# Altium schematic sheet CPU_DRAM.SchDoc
size 381 x 635 mm
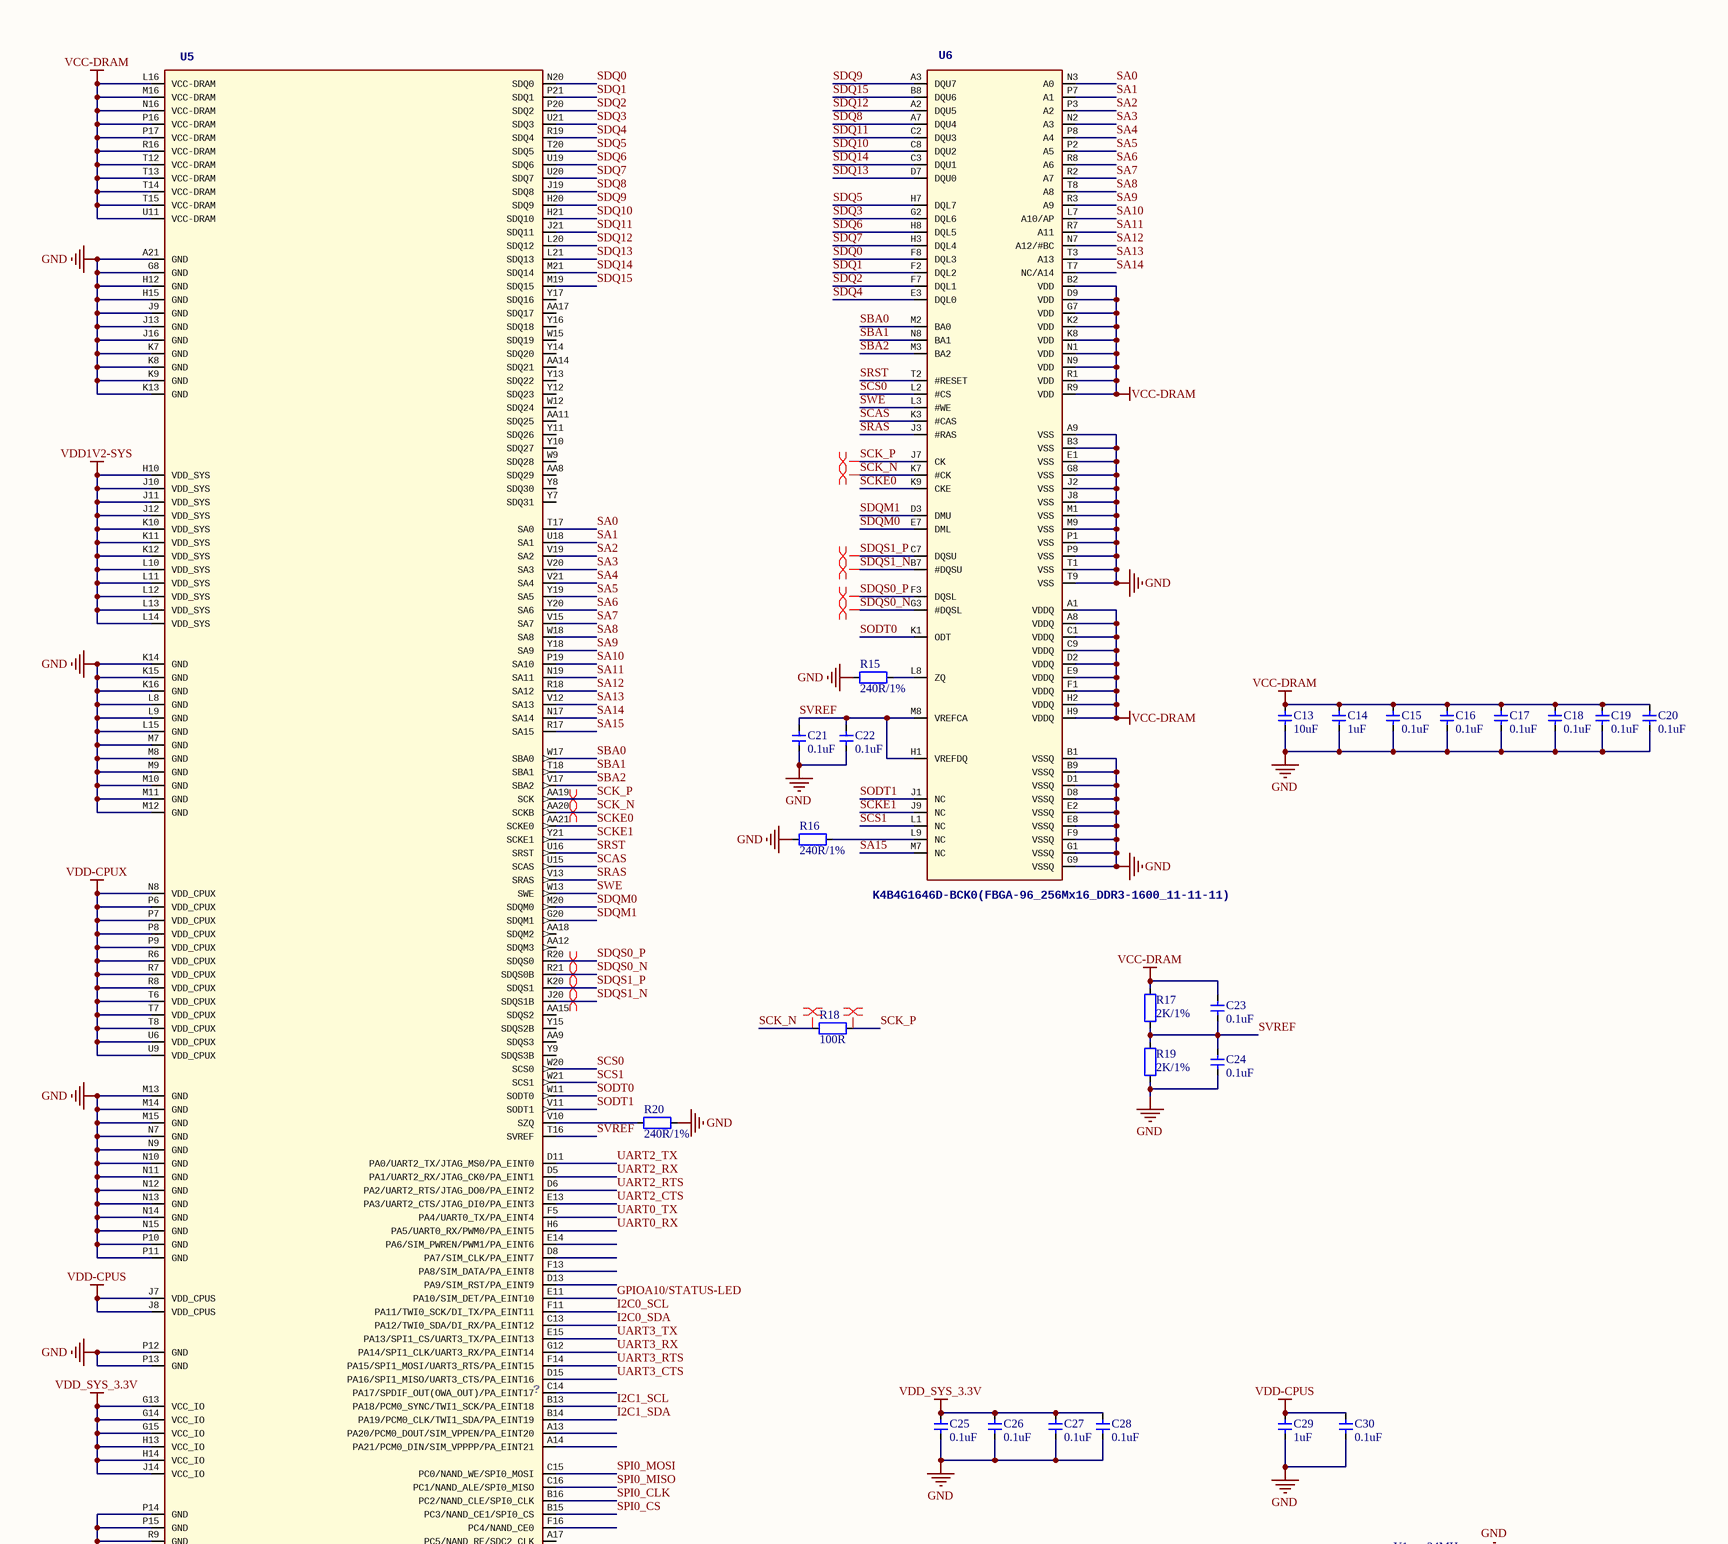
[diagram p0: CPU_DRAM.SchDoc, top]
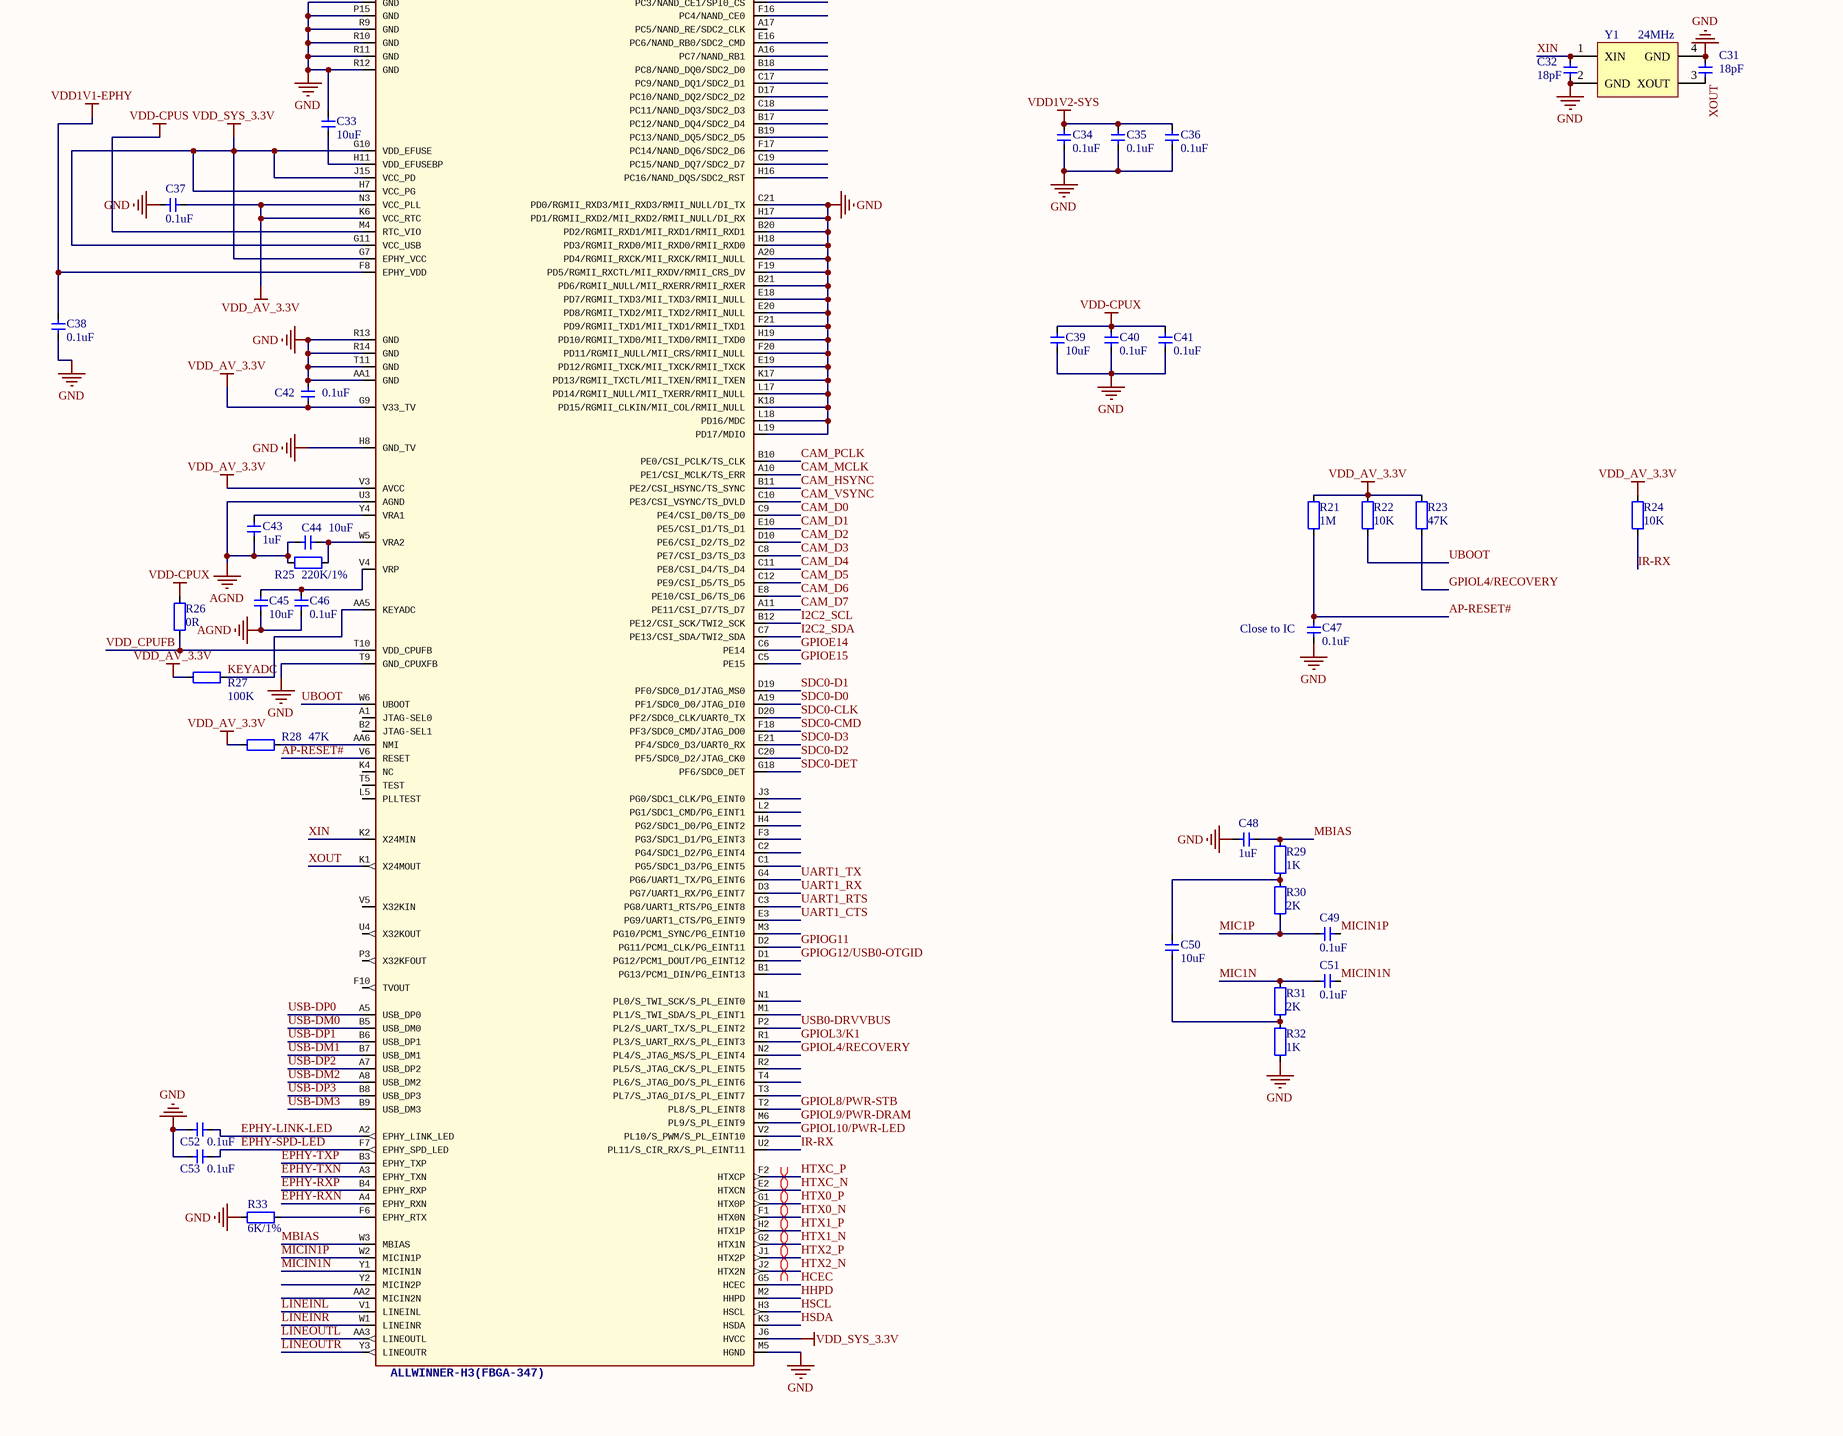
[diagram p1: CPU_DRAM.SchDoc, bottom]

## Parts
C13  10uF  [CAP_0402]
C14  1uF  [CAP_0402]
C15  0.1uF  [CAP_0402]
C16  0.1uF  [CAP_0402]
C17  0.1uF  [CAP_0402]
C18  0.1uF  [CAP_0402]
C19  0.1uF  [CAP_0402]
C20  0.1uF  [CAP_0402]
C21  0.1uF  [CAP_0402]
C22  0.1uF  [CAP_0402]
C23  0.1uF  [CAP_0402]
C24  0.1uF  [CAP_0402]
C25  0.1uF  [CAP_0402]
C26  0.1uF  [CAP_0402]
C27  0.1uF  [CAP_0402]
C28  0.1uF  [CAP_0402]
C29  1uF  [CAP_0402]
C30  0.1uF  [CAP_0402]
C31  18pF  [CAP_0402]
C32  18pF  [CAP_0402]
C33  10uF  [CAP_0402]
C34  0.1uF  [CAP_0402]
C35  0.1uF  [CAP_0402]
C36  0.1uF  [CAP_0402]
C37  0.1uF  [CAP_0402]
C38  0.1uF  [CAP_0402]
C39  10uF  [CAP_0402]
C40  0.1uF  [CAP_0402]
C41  0.1uF  [CAP_0402]
C42  0.1uF  [CAP_0402]
C43  1uF  [CAP_0402]
C44  10uF  [CAP_0402]
C45  10uF  [CAP_0402]
C46  0.1uF  [CAP_0402]
C47  0.1uF  [CAP_0402]
C48  1uF  [CAP_0402]
C49  0.1uF  [CAP_0402]
C50  10uF  [CAP_0402]
C51  0.1uF  [CAP_0402]
C52  0.1uF  [CAP_0402]
C53  0.1uF  [CAP_0402]
R15  240R/1%  [RES_0402]
R16  240R/1%  [RES_0402]
R17  2K/1%  [RES_0402]
R18  100R  [RES_0402]
R19  2K/1%  [RES_0402]
R20  240R/1%  [RES_0402]
R21  1M  [RES_0402]
R22  10K  [RES_0402]
R23  47K  [RES_0402]
R24  10K  [RES_0402]
R25  220K/1%  [RES_0402]
R26  0R  [RES_0402]
R27  100K  [RES_0402]
R28  47K  [RES_0402]
R29  1K  [RES_0402]
R30  2K  [RES_0402]
R31  2K  [RES_0402]
R32  1K  [RES_0402]
R33  6K/1%  [RES_0402]
U5  ALLWINNER-H3(FBGA-347)  [FBGA-347]
U6  K4B4G1646D-BCK0(FBGA-96_256Mx16_DDR3-1600_11-11-11)  [FBGA96(HYNIX_SAMSUNG_512MX16_DDR3)]
Y1  24MHz  [晶振2520]

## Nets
AGND: C43.2 C44.1 C45.1 C46.1 R25.1 U5.U3(AGND)
GND: C13.1 C14.1 C15.1 C16.1 C17.1 C18.1 C19.1 C20.1 C21.1 C22.1 C24.1 C25.1 C26.1 C27.1 C28.1 C29.1 C30.1 C31.2 C32.1 C33.2 C34.1 C35.1 C36.1 C37.2 C38.1 C39.1 C40.1 C41.1 C42.1 C47.1 C48.2 C52.1 C53.1 R15.2 R16.2 R19.1 R20.2 R32.1 R33.1 U5.A20(PD4/RGMII_RXCK/MII_RXCK/RMII_NULL) U5.A21(GND) U5.AA1(GND) U5.B20(PD2/RGMII_RXD1/MII_RXD1/RMII_RXD1) U5.B21(PD6/RGMII_NULL/MII_RXERR/RMII_RXER) U5.C21(PD0/RGMII_RXD3/MII_RXD3/RMII_NULL/DI_TX) U5.E18(PD7/RGMII_TXD3/MII_TXD3/RMII_NULL) U5.E19(PD12/RGMII_TXCK/MII_TXCK/RMII_TXCK) U5.E20(PD8/RGMII_TXD2/MII_TXD2/RMII_NULL) U5.F19(PD5/RGMII_RXCTL/MII_RXDV/RMII_CRS_DV) U5.F20(PD11/RGMII_NULL/MII_CRS/RMII_NULL) U5.F21(PD9/RGMII_TXD1/MII_TXD1/RMII_TXD1) U5.G8(GND) U5.H8(GND_TV) U5.H12(GND) U5.H15(GND) U5.H17(PD1/RGMII_RXD2/MII_RXD2/RMII_NULL/DI_RX) U5.H18(PD3/RGMII_RXD0/MII_RXD0/RMII_RXD0) U5.H19(PD10/RGMII_TXD0/MII_TXD0/RMII_TXD0) U5.J9(GND) U5.J13(GND) U5.J16(GND) U5.K7(GND) U5.K8(GND) U5.K9(GND) U5.K13(GND) U5.K14(GND) U5.K15(GND) U5.K16(GND) U5.K17(PD13/RGMII_TXCTL/MII_TXEN/RMII_TXEN) U5.K18(PD15/RGMII_CLKIN/MII_COL/RMII_NULL) U5.L8(GND) U5.L9(GND) U5.L15(GND) U5.L17(PD14/RGMII_NULL/MII_TXERR/RMII_NULL) U5.L18(PD16/MDC) U5.L19(PD17/MDIO) U5.M5(HGND) U5.M7(GND) U5.M8(GND) U5.M9(GND) U5.M10(GND) U5.M11(GND) U5.M12(GND) U5.M13(GND) U5.M14(GND) U5.M15(GND) U5.N7(GND) U5.N9(GND) U5.N10(GND) U5.N11(GND) U5.N12(GND) U5.N13(GND) U5.N14(GND) U5.N15(GND) U5.P10(GND) U5.P11(GND) U5.P12(GND) U5.P13(GND) U5.P14(GND) U5.P15(GND) U5.R9(GND) U5.R10(GND) U5.R11(GND) U5.R12(GND) U5.R13(GND) U5.R14(GND) U5.T9(GND_CPUXFB) U5.T11(GND) U6.A9(VSS) U6.B1(VSSQ) U6.B3(VSS) U6.B9(VSSQ) U6.D1(VSSQ) U6.D8(VSSQ) U6.E1(VSS) U6.E2(VSSQ) U6.E8(VSSQ) U6.F9(VSSQ) U6.G1(VSSQ) U6.G8(VSS) U6.G9(VSSQ) U6.J2(VSS) U6.J8(VSS) U6.M1(VSS) U6.M9(VSS) U6.P1(VSS) U6.P9(VSS) U6.T1(VSS) U6.T9(VSS) Y1.2(GND) Y1.4(GND)
VCC-DRAM: C13.2 C14.2 C15.2 C16.2 C17.2 C18.2 C19.2 C20.2 C23.2 R17.2 U5.L16(VCC-DRAM) U5.M16(VCC-DRAM) U5.N16(VCC-DRAM) U5.P16(VCC-DRAM) U5.P17(VCC-DRAM) U5.R16(VCC-DRAM) U5.T12(VCC-DRAM) U5.T13(VCC-DRAM) U5.T14(VCC-DRAM) U5.T15(VCC-DRAM) U5.U11(VCC-DRAM) U6.A1(VDDQ) U6.A8(VDDQ) U6.B2(VDD) U6.C1(VDDQ) U6.C9(VDDQ) U6.D2(VDDQ) U6.D9(VDD) U6.E9(VDDQ) U6.F1(VDDQ) U6.G7(VDD) U6.H2(VDDQ) U6.H9(VDDQ) U6.K2(VDD) U6.K8(VDD) U6.N1(VDD) U6.N9(VDD) U6.R1(VDD) U6.R9(VDD)
VDD1V1-EPHY: C38.2 U5.F8(EPHY_VDD)
VDD1V2-SYS: C34.2 C35.2 C36.2 U5.H10(VDD_SYS) U5.J10(VDD_SYS) U5.J11(VDD_SYS) U5.J12(VDD_SYS) U5.K10(VDD_SYS) U5.K11(VDD_SYS) U5.K12(VDD_SYS) U5.L10(VDD_SYS) U5.L11(VDD_SYS) U5.L12(VDD_SYS) U5.L13(VDD_SYS) U5.L14(VDD_SYS)
VDD-CPUS: C29.2 C30.2 U5.J7(VDD_CPUS) U5.J8(VDD_CPUS) U5.M4(RTC_VIO)
VDD-CPUX: C39.2 C40.2 C41.2 R26.2 U5.N8(VDD_CPUX) U5.P6(VDD_CPUX) U5.P7(VDD_CPUX) U5.P8(VDD_CPUX) U5.P9(VDD_CPUX) U5.R6(VDD_CPUX) U5.R7(VDD_CPUX) U5.R8(VDD_CPUX) U5.T6(VDD_CPUX) U5.T7(VDD_CPUX) U5.T8(VDD_CPUX) U5.U6(VDD_CPUX) U5.U9(VDD_CPUX)
VDD_AV_3.3V: C37.1 C42.2 R21.2 R22.2 R23.2 R24.2 R27.1 R28.1 U5.G9(V33_TV) U5.K6(VCC_RTC) U5.N3(VCC_PLL) U5.V3(AVCC)
VDD_SYS_3.3V: C25.2 C26.2 C27.2 C28.2 U5.G7(EPHY_VCC) U5.G10(VDD_EFUSE) U5.G11(VCC_USB) U5.G13(VCC_IO) U5.G14(VCC_IO) U5.G15(VCC_IO) U5.H7(VCC_PG) U5.H13(VCC_IO) U5.H14(VCC_IO) U5.J6(HVCC) U5.J14(VCC_IO) U5.J15(VCC_PD)
AP-RESET#: C47.2 R21.1 U5.V6(RESET)
CAM_D0: U5.C9(PE4/CSI_D0/TS_D0)
CAM_D1: U5.E10(PE5/CSI_D1/TS_D1)
CAM_D2: U5.D10(PE6/CSI_D2/TS_D2)
CAM_D3: U5.C8(PE7/CSI_D3/TS_D3)
CAM_D4: U5.C11(PE8/CSI_D4/TS_D4)
CAM_D5: U5.C12(PE9/CSI_D5/TS_D5)
CAM_D6: U5.E8(PE10/CSI_D6/TS_D6)
CAM_D7: U5.A11(PE11/CSI_D7/TS_D7)
CAM_HSYNC: U5.B11(PE2/CSI_HSYNC/TS_SYNC)
CAM_MCLK: U5.A10(PE1/CSI_MCLK/TS_ERR)
CAM_PCLK: U5.B10(PE0/CSI_PCLK/TS_CLK)
CAM_VSYNC: U5.C10(PE3/CSI_VSYNC/TS_DVLD)
EPHY-LINK-LED: C52.2 U5.A2(EPHY_LINK_LED)
EPHY-RXN: U5.A4(EPHY_RXN)
EPHY-RXP: U5.B4(EPHY_RXP)
EPHY-SPD-LED: C53.2 U5.F7(EPHY_SPD_LED)
EPHY-TXN: U5.A3(EPHY_TXN)
EPHY-TXP: U5.B3(EPHY_TXP)
GPIOA10/STATUS-LED: U5.E11(PA10/SIM_DET/PA_EINT10)
GPIOE14: U5.C6(PE14)
GPIOE15: U5.C5(PE15)
GPIOG11: U5.D2(PG11/PCM1_CLK/PG_EINT11)
GPIOG12/USB0-OTGID: U5.D1(PG12/PCM1_DOUT/PG_EINT12)
GPIOL3/K1: U5.R1(PL3/S_UART_RX/S_PL_EINT3)
GPIOL4/RECOVERY: R23.1 U5.N2(PL4/S_JTAG_MS/S_PL_EINT4)
GPIOL8/PWR-STB: U5.T2(PL8/S_PL_EINT8)
GPIOL9/PWR-DRAM: U5.M6(PL9/S_PL_EINT9)
GPIOL10/PWR-LED: U5.V2(PL10/S_PWM/S_PL_EINT10)
HCEC: U5.G5(HCEC)
HHPD: U5.M2(HHPD)
HSCL: U5.H3(HSCL)
HSDA: U5.K3(HSDA)
HTX0_N: U5.F1(HTX0N)
HTX0_P: U5.G1(HTX0P)
HTX1_N: U5.G2(HTX1N)
HTX1_P: U5.H2(HTX1P)
HTX2_N: U5.J2(HTX2N)
HTX2_P: U5.J1(HTX2P)
HTXC_N: U5.E2(HTXCN)
HTXC_P: U5.F2(HTXCP)
I2C0_SCL: U5.F11(PA11/TWI0_SCK/DI_TX/PA_EINT11)
I2C0_SDA: U5.C13(PA12/TWI0_SDA/DI_RX/PA_EINT12)
I2C1_SCL: U5.B13(PA18/PCM0_SYNC/TWI1_SCK/PA_EINT18)
I2C1_SDA: U5.B14(PA19/PCM0_CLK/TWI1_SDA/PA_EINT19)
I2C2_SCL: U5.B12(PE12/CSI_SCK/TWI2_SCK)
I2C2_SDA: U5.C7(PE13/CSI_SDA/TWI2_SDA)
IR-RX: R24.1 U5.U2(PL11/S_CIR_RX/S_PL_EINT11)
KEYADC: R27.2 U5.AA5(KEYADC)
LINEINL: U5.V1(LINEINL)
LINEINR: U5.W1(LINEINR)
LINEOUTL: U5.AA3(LINEOUTL)
LINEOUTR: U5.Y3(LINEOUTR)
MBIAS: C48.1 R29.2 U5.W3(MBIAS)
MIC1N: C51.2 R31.2
MIC1P: C49.2 R30.1
MICIN1N: C51.1 U5.Y1(MICIN1N)
MICIN1P: C49.1 U5.W2(MICIN1P)
SA0: U5.T17(SA0) U6.N3(A0)
SA1: U5.U18(SA1) U6.P7(A1)
SA2: U5.V19(SA2) U6.P3(A2)
SA3: U5.V20(SA3) U6.N2(A3)
SA4: U5.V21(SA4) U6.P8(A4)
SA5: U5.Y19(SA5) U6.P2(A5)
SA6: U5.Y20(SA6) U6.R8(A6)
SA7: U5.V15(SA7) U6.R2(A7)
SA8: U5.W18(SA8) U6.T8(A8)
SA9: U5.Y18(SA9) U6.R3(A9)
SA10: U5.P19(SA10) U6.L7(A10/AP)
SA11: U5.N19(SA11) U6.R7(A11)
SA12: U5.R18(SA12) U6.N7(A12/#BC)
SA13: U5.V12(SA13) U6.T3(A13)
SA14: U5.N17(SA14) U6.T7(NC/A14)
SA15: U5.R17(SA15) U6.M7(NC)
SBA0: U5.W17(SBA0) U6.M2(BA0)
SBA1: U5.T18(SBA1) U6.N8(BA1)
SBA2: U5.V17(SBA2) U6.M3(BA2)
SCAS: U5.U15(SCAS) U6.K3(#CAS)
SCK_N: R18.1 U5.AA20(SCKB) U6.K7(#CK)
SCK_P: R18.2 U5.AA19(SCK) U6.J7(CK)
SCKE0: U5.AA21(SCKE0) U6.K9(CKE)
SCKE1: U5.Y21(SCKE1) U6.J9(NC)
SCS0: U5.W20(SCS0) U6.L2(#CS)
SCS1: U5.W21(SCS1) U6.L1(NC)
SDC0-CLK: U5.D20(PF2/SDC0_CLK/UART0_TX)
SDC0-CMD: U5.F18(PF3/SDC0_CMD/JTAG_DO0)
SDC0-D0: U5.A19(PF1/SDC0_D0/JTAG_DI0)
SDC0-D1: U5.D19(PF0/SDC0_D1/JTAG_MS0)
SDC0-D2: U5.C20(PF5/SDC0_D2/JTAG_CK0)
SDC0-D3: U5.E21(PF4/SDC0_D3/UART0_RX)
SDC0-DET: U5.G18(PF6/SDC0_DET)
SDQ0: U5.N20(SDQ0) U6.F8(DQL3)
SDQ1: U5.P21(SDQ1) U6.F2(DQL2)
SDQ2: U5.P20(SDQ2) U6.F7(DQL1)
SDQ3: U5.U21(SDQ3) U6.G2(DQL6)
SDQ4: U5.R19(SDQ4) U6.E3(DQL0)
SDQ5: U5.T20(SDQ5) U6.H7(DQL7)
SDQ6: U5.U19(SDQ6) U6.H8(DQL5)
SDQ7: U5.U20(SDQ7) U6.H3(DQL4)
SDQ8: U5.J19(SDQ8) U6.A7(DQU4)
SDQ9: U5.H20(SDQ9) U6.A3(DQU7)
SDQ10: U5.H21(SDQ10) U6.C8(DQU2)
SDQ11: U5.J21(SDQ11) U6.C2(DQU3)
SDQ12: U5.L20(SDQ12) U6.A2(DQU5)
SDQ13: U5.L21(SDQ13) U6.D7(DQU0)
SDQ14: U5.M21(SDQ14) U6.C3(DQU1)
SDQ15: U5.M19(SDQ15) U6.B8(DQU6)
SDQM0: U5.M20(SDQM0) U6.E7(DML)
SDQM1: U5.G20(SDQM1) U6.D3(DMU)
SDQS0_N: U5.R21(SDQS0B) U6.G3(#DQSL)
SDQS0_P: U5.R20(SDQS0) U6.F3(DQSL)
SDQS1_N: U5.J20(SDQS1B) U6.B7(#DQSU)
SDQS1_P: U5.K20(SDQS1) U6.C7(DQSU)
SODT0: U5.W11(SODT0) U6.K1(ODT)
SODT1: U5.V11(SODT1) U6.J1(NC)
SPI0_CLK: U5.B16(PC2/NAND_CLE/SPI0_CLK)
SPI0_CS: U5.B15(PC3/NAND_CE1/SPI0_CS)
SPI0_MISO: U5.C16(PC1/NAND_ALE/SPI0_MISO)
SPI0_MOSI: U5.C15(PC0/NAND_WE/SPI0_MOSI)
SRAS: U5.V13(SRAS) U6.J3(#RAS)
SRST: U5.U16(SRST) U6.T2(#RESET)
SVREF: C21.2 C22.2 C23.1 C24.2 R17.1 R19.2 U5.T16(SVREF) U6.H1(VREFDQ) U6.M8(VREFCA)
SWE: U5.W13(SWE) U6.L3(#WE)
UART0_RX: U5.H6(PA5/UART0_RX/PWM0/PA_EINT5)
UART0_TX: U5.F5(PA4/UART0_TX/PA_EINT4)
UART1_CTS: U5.E3(PG9/UART1_CTS/PG_EINT9)
UART1_RTS: U5.C3(PG8/UART1_RTS/PG_EINT8)
UART1_RX: U5.D3(PG7/UART1_RX/PG_EINT7)
UART1_TX: U5.G4(PG6/UART1_TX/PG_EINT6)
UART2_CTS: U5.E13(PA3/UART2_CTS/JTAG_DI0/PA_EINT3)
UART2_RTS: U5.D6(PA2/UART2_RTS/JTAG_DO0/PA_EINT2)
UART2_RX: U5.D5(PA1/UART2_RX/JTAG_CK0/PA_EINT1)
UART2_TX: U5.D11(PA0/UART2_TX/JTAG_MS0/PA_EINT0)
UART3_CTS: U5.D15(PA16/SPI1_MISO/UART3_CTS/PA_EINT16)
UART3_RTS: U5.F14(PA15/SPI1_MOSI/UART3_RTS/PA_EINT15)
UART3_RX: U5.G12(PA14/SPI1_CLK/UART3_RX/PA_EINT14)
UART3_TX: U5.E15(PA13/SPI1_CS/UART3_TX/PA_EINT13)
UBOOT: R22.1 U5.W6(UBOOT)
USB0-DRVVBUS: U5.P2(PL2/S_UART_TX/S_PL_EINT2)
USB-DM0: U5.B5(USB_DM0)
USB-DM1: U5.B7(USB_DM1)
USB-DM2: U5.A8(USB_DM2)
USB-DM3: U5.B9(USB_DM3)
USB-DP0: U5.A5(USB_DP0)
USB-DP1: U5.B6(USB_DP1)
USB-DP2: U5.A7(USB_DP2)
USB-DP3: U5.B8(USB_DP3)
VDD_CPUFB: R26.1 U5.T10(VDD_CPUFB)
XIN: C32.2 U5.K2(X24MIN) Y1.1(XIN)
XOUT: C31.1 U5.K1(X24MOUT) Y1.3(XOUT)
NetC33_1: C33.1 U5.H11(VDD_EFUSEBP)
NetC43_1: C43.1 U5.Y4(VRA1)
NetC44_2: C44.2 R25.2 U5.W5(VRA2)
NetC45_2: C45.2 C46.2 U5.V4(VRP)
NetC50_1: C50.1 R31.1 R32.2
NetC50_2: C50.2 R29.1 R30.2
NetR15_1: R15.1 U6.L8(ZQ)
NetR16_1: R16.1 U6.L9(NC)
NetR20_1: R20.1 U5.V10(SZQ)
NetR28_2: R28.2 U5.AA6(NMI)
NetR33_2: R33.2 U5.F6(EPHY_RTX)

Not connected (* = marked no-connect by the designer): U5 A1(JTAG-SEL0) A13(PA20/PCM0_DOUT/SIM_VPPEN/PA_EINT20) A14(PA21/PCM0_DIN/SIM_VPPPP/PA_EINT21) A16(PC7/NAND_RB1) A17(PC5/NAND_RE/SDC2_CLK) AA2(MICIN2N) AA8(SDQ29) AA9(SDQS3) AA11(SDQ25) AA12(SDQM3) AA14(SDQ21) AA15(SDQS2) AA17(SDQ17) AA18(SDQM2) B1(PG13/PCM1_DIN/PG_EINT13) B2(JTAG-SEL1) B17(PC12/NAND_DQ4/SDC2_D4) B18(PC8/NAND_DQ0/SDC2_D0) B19(PC13/NAND_DQ5/SDC2_D5) C1(PG5/SDC1_D3/PG_EINT5) C2(PG4/SDC1_D2/PG_EINT4) C14(PA17/SPDIF_OUT(OWA_OUT)/PA_EINT17) C17(PC9/NAND_DQ1/SDC2_D1) C18(PC11/NAND_DQ3/SDC2_D3) C19(PC15/NAND_DQ7/SDC2_D7) D8(PA7/SIM_CLK/PA_EINT7) D13(PA9/SIM_RST/PA_EINT9) D17(PC10/NAND_DQ2/SDC2_D2) E14(PA6/SIM_PWREN/PWM1/PA_EINT6) E16(PC6/NAND_RB0/SDC2_CMD) F3(PG3/SDC1_D1/PG_EINT3) F10(TVOUT) F13(PA8/SIM_DATA/PA_EINT8) F16(PC4/NAND_CE0) F17(PC14/NAND_DQ6/SDC2_D6) H4(PG2/SDC1_D0/PG_EINT2) H16(PC16/NAND_DQS/SDC2_RST) J3(PG0/SDC1_CLK/PG_EINT0) K4(NC) L2(PG1/SDC1_CMD/PG_EINT1) L5(PLLTEST) M1(PL1/S_TWI_SDA/S_PL_EINT1) M3(PG10/PCM1_SYNC/PG_EINT10) N1(PL0/S_TWI_SCK/S_PL_EINT0) P3(X32KFOUT) R2(PL5/S_JTAG_CK/S_PL_EINT5) T3(PL7/S_JTAG_DI/S_PL_EINT7) T4(PL6/S_JTAG_DO/S_PL_EINT6) T5(TEST) U4(X32KOUT) V5(X32KIN) W9(SDQ28) W12(SDQ24) W15(SDQ19) Y2(MICIN2P) Y7(SDQ31) Y8(SDQ30) Y9(SDQS3B) Y10(SDQ27) Y11(SDQ26) Y12(SDQ23) Y13(SDQ22) Y14(SDQ20) Y15(SDQS2B) Y16(SDQ18) Y17(SDQ16)

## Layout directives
differential pair: HTX0_N, HTX0_P, HTX1_N, HTX1_P, HTX2_N, HTX2_P, HTXC_N, HTXC_P, SCK_N, SCK_P, SDQS0_N, SDQS0_P, SDQS1_N, SDQS1_P

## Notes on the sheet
- (near C47) Close to IC

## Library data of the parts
C13-C53 = 电容-0402: Capacitor; Value: 0.1u
R15-R33 = 电阻-0402: Resistor; Value: 22R
U6 = K4B8G1646Q-MYK0(FBGA-96_512MX16_DDR3-1600)
Y1 = 晶振-4Pin-无源: 2520无源; MF: ECS International; MP: ECS-3225S30-240-EN-TR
